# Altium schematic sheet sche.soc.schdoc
size 594 x 419 mm; Symbol: Sheet-Symbol_A4; Border: 1; Title Block Position: 3; Width: 2338; Height: 1652; Region Start: 1; X Region Count: 6; Y Region Count: 4; Blade Width: 10; Title Block: 1; @Board Name: NandFlash; @Create Time: 14:00:03; @Update Time: 18:33:35; Company: 嘉立创EDA; Version: V1.0; Page Size: A4; @Project Name: 木马派(Mumap) Linux卡片电脑-RV1106G; @Page Count: 10; @Update Date: 2025-03-03; @Create Date: 2024-10-19; @Schematic Name: Schematic1; @Page No: 1; @Page Name: RV1106G; Device: Sheet-Symbol_A4
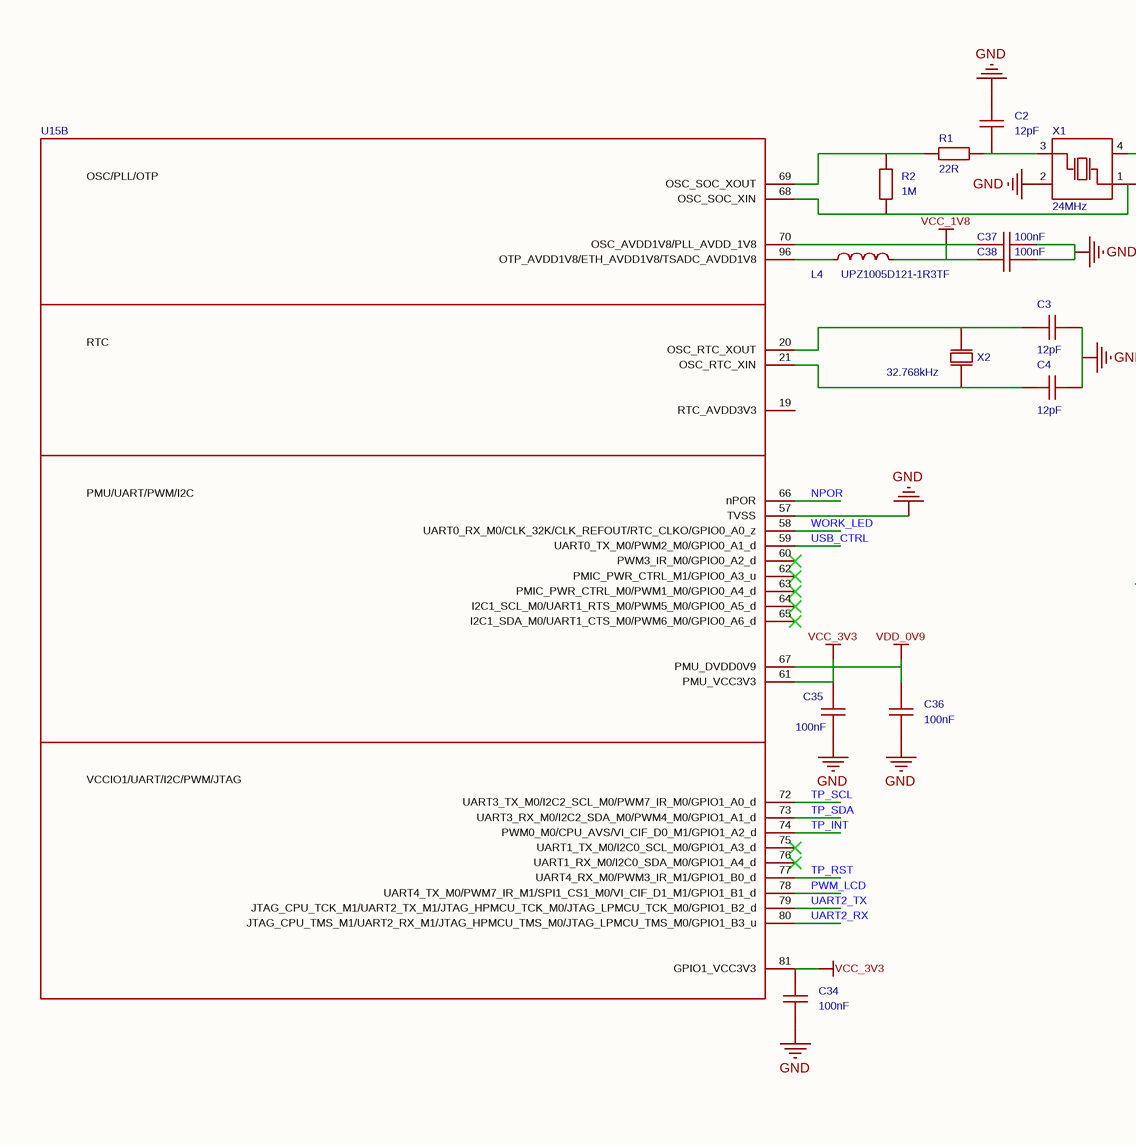
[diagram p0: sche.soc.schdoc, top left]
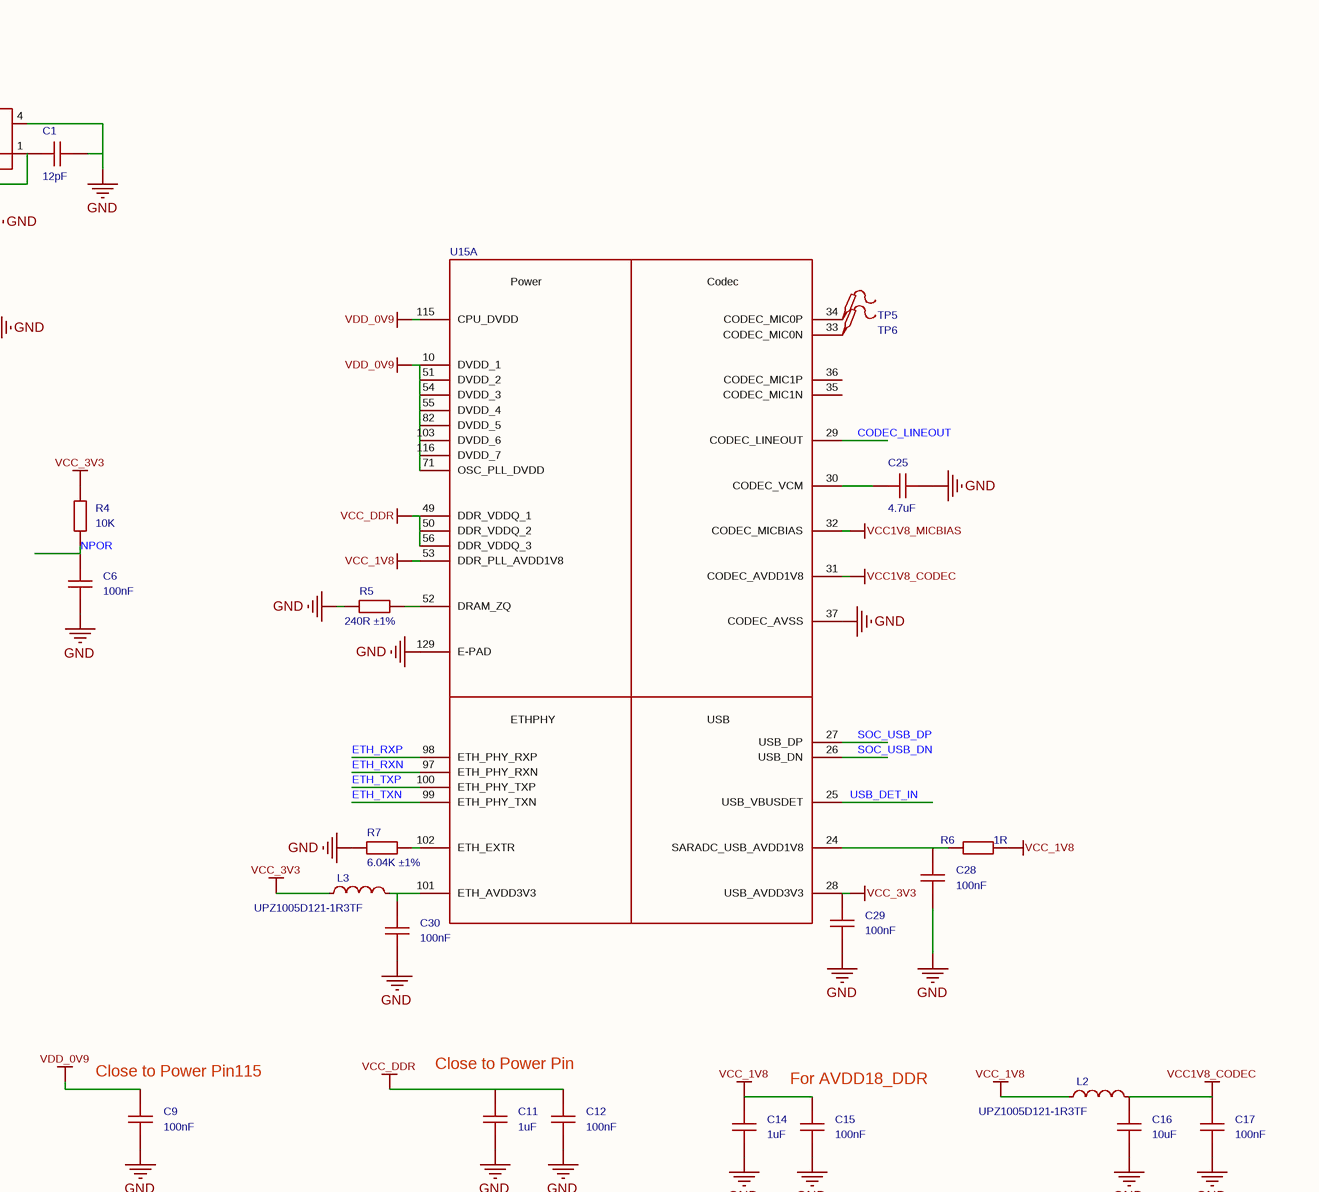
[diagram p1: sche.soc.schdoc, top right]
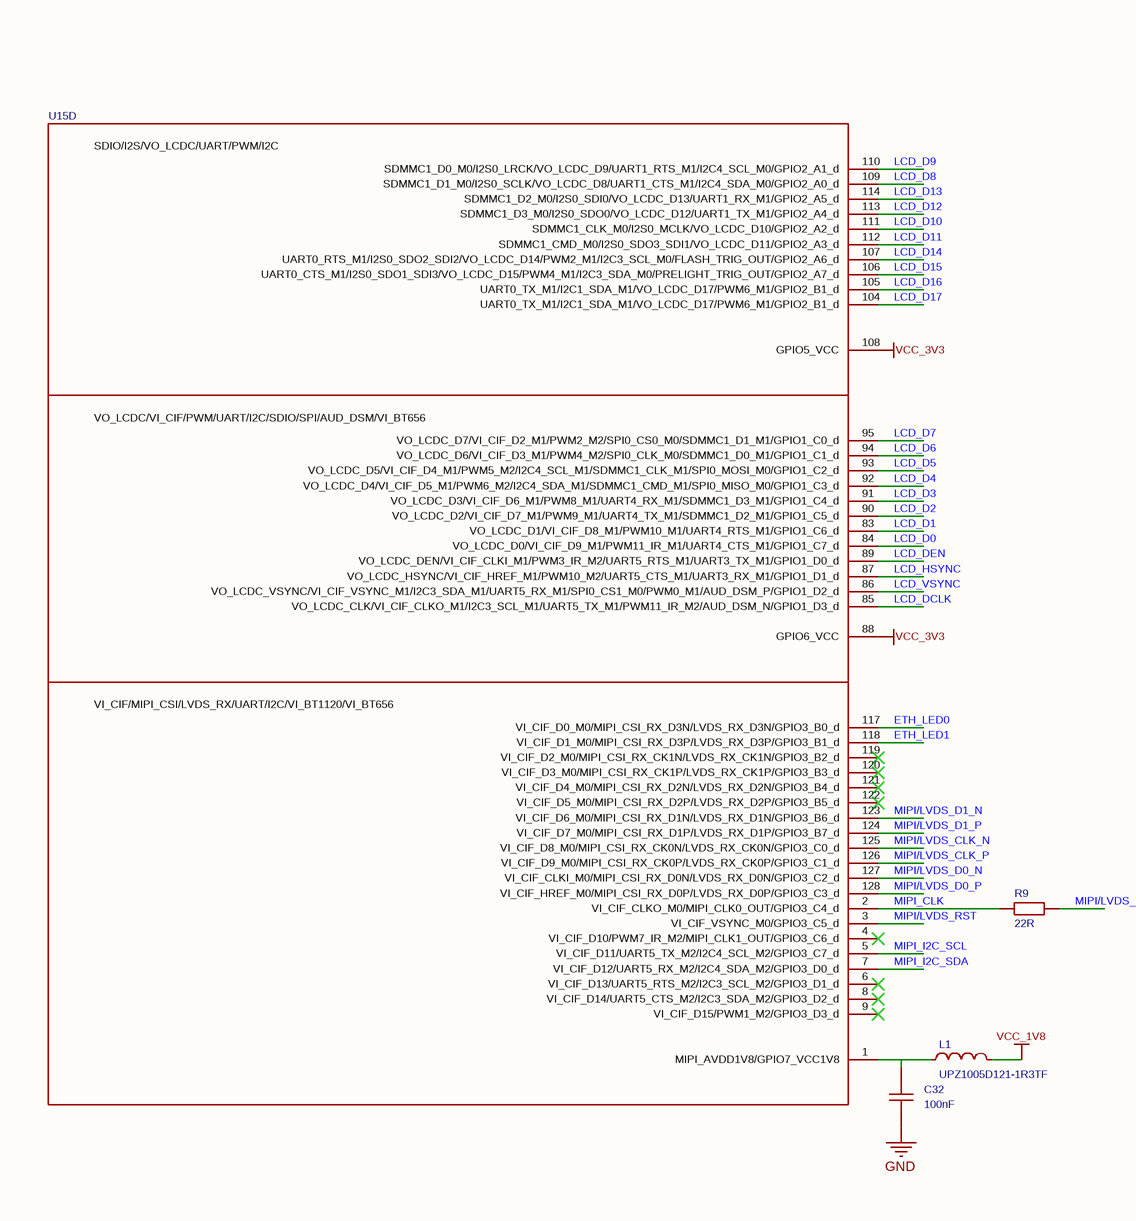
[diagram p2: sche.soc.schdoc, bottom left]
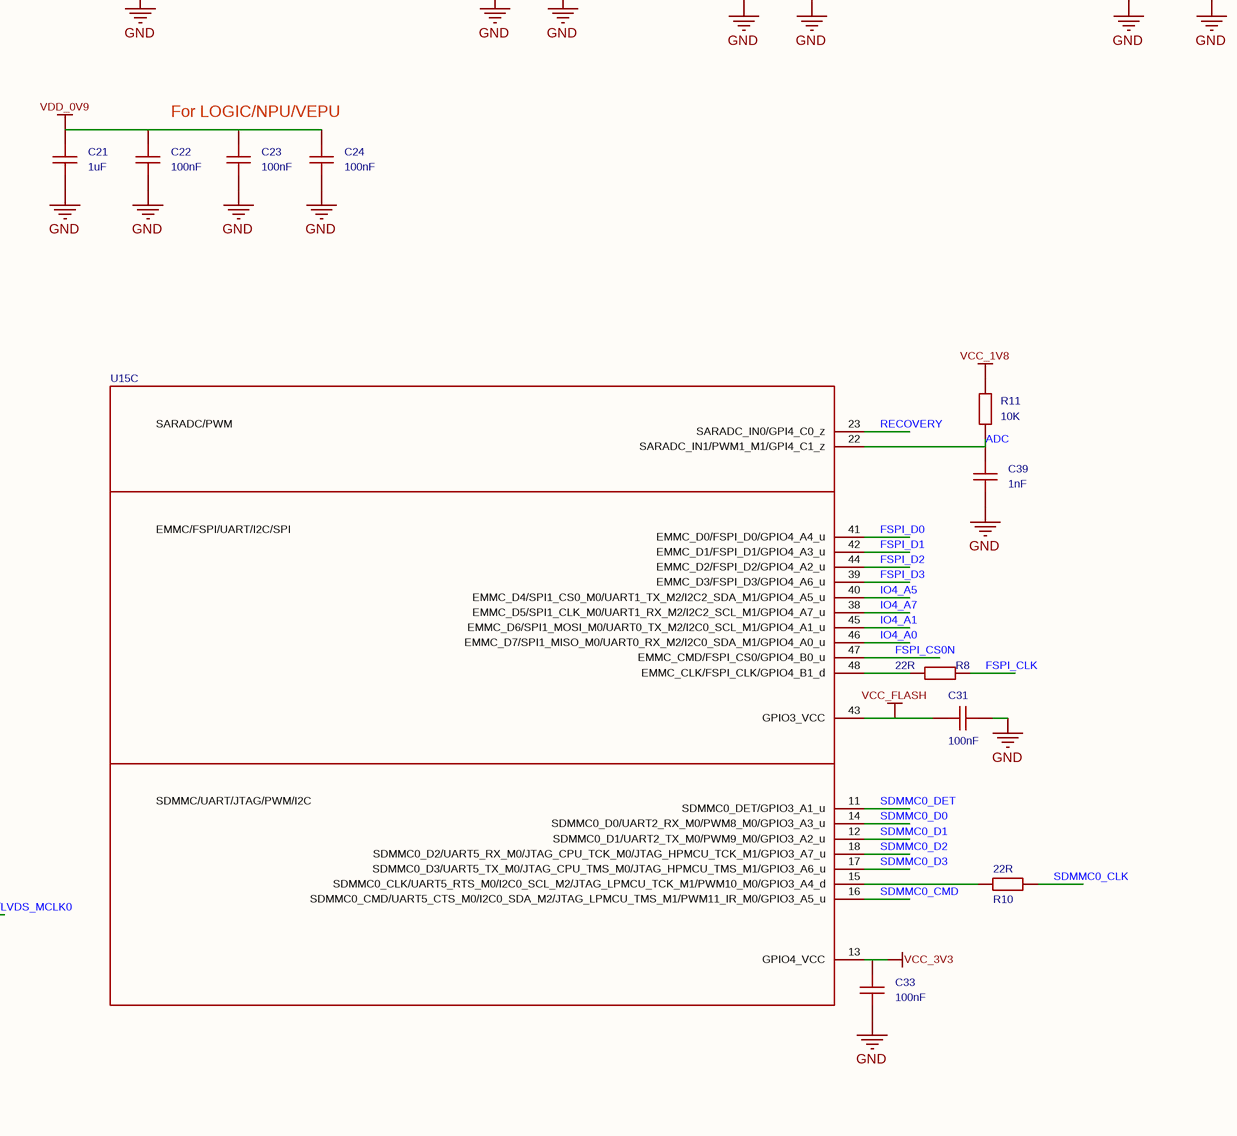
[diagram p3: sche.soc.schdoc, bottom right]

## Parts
C1  12pF  [C0402]
C2  12pF  [C0402]
C3  12pF  [C0402]
C4  12pF  [C0402]
C6  100nF  [C0402]
C9  100nF  [C0402]
C11  1uF  [C0402]
C12  100nF  [C0402]
C14  1uF  [C0402]
C15  100nF  [C0402]
C16  10uF  [C0603]
C17  100nF  [C0402]
C21  1uF  [C0402]
C22  100nF  [C0402]
C23  100nF  [C0402]
C24  100nF  [C0402]
C25  4.7uF  [C0603]
C28  100nF  [C0402]
C29  100nF  [C0402]
C30  100nF  [C0402]
C31  100nF  [C0402]
C32  100nF  [C0402]
C33  100nF  [C0402]
C34  100nF  [C0402]
C35  100nF  [C0402]
C36  100nF  [C0402]
C37  100nF  [C0402]
C38  100nF  [C0402]
C39  1nF  [C0402]
L1  UPZ1005D121-1R3TF  [L0402]
L2  UPZ1005D121-1R3TF  [L0402]
L3  UPZ1005D121-1R3TF  [L0402]
L4  UPZ1005D121-1R3TF  [L0402]
R1  22R  [R0402]
R2  1M  [R0402]
R4  10K  [R0402]
R5  240R ±1%  [R0402]
R6  1R  [R0402]
R7  6.04K ±1%  [R0402]
R8  22R  [R0402]
R9  22R  [R0402]
R10  22R  [R0402]
R11  10K  [R0402]
TP5  (no value)  [Test-Point-0.5mm]
TP6  (no value)  [Test-Point-0.5mm]
U15  (no value)  [QFN-128_L12.3-W12.3-P0.35-TL-EP7.0-1]  (parts A,B,C,D of 4)
X1  24MHz  [CRYSTAL-SMD_4P-L2.0-W1.6-BL-A]
X2  32.768kHz  [CRYSTAL-SMD_2P-L2.0-W1.2]

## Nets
GND: C1.1 C2.2 C3.1 C4.1 C6.1 C9.1 C11.1 C12.1 C14.1 C15.1 C16.1 C17.1 C21.1 C22.1 C23.1 C24.1 C25.2 C28.1 C29.1 C30.1 C31.1 C32.1 C33.1 C34.1 C35.1 C36.1 C37.2 C38.2 C39.1 R5.1 R7.1 U15.37(CODEC_AVSS) U15.57(TVSS) U15.129(E-PAD) X1.2(GND) X1.4(GND)
VCC1V8_CODEC: C16.2 C17.2 L2.2 U15.31(CODEC_AVDD1V8)
VCC1V8_MICBIAS: U15.32(CODEC_MICBIAS)
VCC_1V8: C14.2 C15.2 C37.1 C38.1 L1.2 L2.1 L4.2 R6.2 R11.2 U15.53(DDR_PLL_AVDD1V8) U15.70(OSC_AVDD1V8/PLL_AVDD_1V8)
VCC_3V3: C29.2 C33.2 C34.2 C35.2 L3.1 R4.2 U15.13(GPIO4_VCC) U15.28(USB_AVDD3V3) U15.61(PMU_VCC3V3) U15.81(GPIO1_VCC3V3) U15.88(GPIO6_VCC) U15.108(GPIO5_VCC)
VCC_DDR: C11.2 C12.2 U15.49(DDR_VDDQ_1) U15.50(DDR_VDDQ_2) U15.56(DDR_VDDQ_3)
VCC_FLASH: C31.2 U15.43(GPIO3_VCC)
VDD_0V9: C9.2 C21.2 C22.2 C23.2 C24.2 C36.2 U15.10(DVDD_1) U15.51(DVDD_2) U15.54(DVDD_3) U15.55(DVDD_4) U15.67(PMU_DVDD0V9) U15.71(OSC_PLL_DVDD) U15.82(DVDD_5) U15.103(DVDD_6) U15.115(CPU_DVDD) U15.116(DVDD_7)
ADC: C39.2 R11.1 U15.22(SARADC_IN1/PWM1_M1/GPI4_C1_z)
CODEC_LINEOUT: U15.29(CODEC_LINEOUT)
ETH_LED0: U15.117(VI_CIF_D0_M0/MIPI_CSI_RX_D3N/LVDS_RX_D3N/GPIO3_B0_d)
ETH_LED1: U15.118(VI_CIF_D1_M0/MIPI_CSI_RX_D3P/LVDS_RX_D3P/GPIO3_B1_d)
ETH_RXN: U15.97(ETH_PHY_RXN)
ETH_RXP: U15.98(ETH_PHY_RXP)
ETH_TXN: U15.99(ETH_PHY_TXN)
ETH_TXP: U15.100(ETH_PHY_TXP)
FSPI_CLK: R8.2
FSPI_CS0N: U15.47(EMMC_CMD/FSPI_CS0/GPIO4_B0_u)
FSPI_D0: U15.41(EMMC_D0/FSPI_D0/GPIO4_A4_u)
FSPI_D1: U15.42(EMMC_D1/FSPI_D1/GPIO4_A3_u)
FSPI_D2: U15.44(EMMC_D2/FSPI_D2/GPIO4_A2_u)
FSPI_D3: U15.39(EMMC_D3/FSPI_D3/GPIO4_A6_u)
IO4_A0: U15.46(EMMC_D7/SPI1_MISO_M0/UART0_RX_M2/I2C0_SDA_M1/GPIO4_A0_u)
IO4_A1: U15.45(EMMC_D6/SPI1_MOSI_M0/UART0_TX_M2/I2C0_SCL_M1/GPIO4_A1_u)
IO4_A5: U15.40(EMMC_D4/SPI1_CS0_M0/UART1_TX_M2/I2C2_SDA_M1/GPIO4_A5_u)
IO4_A7: U15.38(EMMC_D5/SPI1_CLK_M0/UART1_RX_M2/I2C2_SCL_M1/GPIO4_A7_u)
LCD_D0: U15.84(VO_LCDC_D0/VI_CIF_D9_M1/PWM11_IR_M1/UART4_CTS_M1/GPIO1_C7_d)
LCD_D1: U15.83(VO_LCDC_D1/VI_CIF_D8_M1/PWM10_M1/UART4_RTS_M1/GPIO1_C6_d)
LCD_D2: U15.90(VO_LCDC_D2/VI_CIF_D7_M1/PWM9_M1/UART4_TX_M1/SDMMC1_D2_M1/GPIO1_C5_d)
LCD_D3: U15.91(VO_LCDC_D3/VI_CIF_D6_M1/PWM8_M1/UART4_RX_M1/SDMMC1_D3_M1/GPIO1_C4_d)
LCD_D4: U15.92(VO_LCDC_D4/VI_CIF_D5_M1/PWM6_M2/I2C4_SDA_M1/SDMMC1_CMD_M1/SPI0_MISO_M0/GPIO1_C3_d)
LCD_D5: U15.93(VO_LCDC_D5/VI_CIF_D4_M1/PWM5_M2/I2C4_SCL_M1/SDMMC1_CLK_M1/SPI0_MOSI_M0/GPIO1_C2_d)
LCD_D6: U15.94(VO_LCDC_D6/VI_CIF_D3_M1/PWM4_M2/SPI0_CLK_M0/SDMMC1_D0_M1/GPIO1_C1_d)
LCD_D7: U15.95(VO_LCDC_D7/VI_CIF_D2_M1/PWM2_M2/SPI0_CS0_M0/SDMMC1_D1_M1/GPIO1_C0_d)
LCD_D8: U15.109(SDMMC1_D1_M0/I2S0_SCLK/VO_LCDC_D8/UART1_CTS_M1/I2C4_SDA_M0/GPIO2_A0_d)
LCD_D9: U15.110(SDMMC1_D0_M0/I2S0_LRCK/VO_LCDC_D9/UART1_RTS_M1/I2C4_SCL_M0/GPIO2_A1_d)
LCD_D10: U15.111(SDMMC1_CLK_M0/I2S0_MCLK/VO_LCDC_D10/GPIO2_A2_d)
LCD_D11: U15.112(SDMMC1_CMD_M0/I2S0_SDO3_SDI1/VO_LCDC_D11/GPIO2_A3_d)
LCD_D12: U15.113(SDMMC1_D3_M0/I2S0_SDO0/VO_LCDC_D12/UART1_TX_M1/GPIO2_A4_d)
LCD_D13: U15.114(SDMMC1_D2_M0/I2S0_SDI0/VO_LCDC_D13/UART1_RX_M1/GPIO2_A5_d)
LCD_D14: U15.107(UART0_RTS_M1/I2S0_SDO2_SDI2/VO_LCDC_D14/PWM2_M1/I2C3_SCL_M0/FLASH_TRIG_OUT/GPIO2_A6_d)
LCD_D15: U15.106(UART0_CTS_M1/I2S0_SDO1_SDI3/VO_LCDC_D15/PWM4_M1/I2C3_SDA_M0/PRELIGHT_TRIG_OUT/GPIO2_A7_d)
LCD_D16: U15.105(UART0_TX_M1/I2C1_SDA_M1/VO_LCDC_D17/PWM6_M1/GPIO2_B1_d)
LCD_D17: U15.104(UART0_TX_M1/I2C1_SDA_M1/VO_LCDC_D17/PWM6_M1/GPIO2_B1_d)
LCD_DCLK: U15.85(VO_LCDC_CLK/VI_CIF_CLKO_M1/I2C3_SCL_M1/UART5_TX_M1/PWM11_IR_M2/AUD_DSM_N/GPIO1_D3_d)
LCD_DEN: U15.89(VO_LCDC_DEN/VI_CIF_CLKI_M1/PWM3_IR_M2/UART5_RTS_M1/UART3_TX_M1/GPIO1_D0_d)
LCD_HSYNC: U15.87(VO_LCDC_HSYNC/VI_CIF_HREF_M1/PWM10_M2/UART5_CTS_M1/UART3_RX_M1/GPIO1_D1_d)
LCD_VSYNC: U15.86(VO_LCDC_VSYNC/VI_CIF_VSYNC_M1/I2C3_SDA_M1/UART5_RX_M1/SPI0_CS1_M0/PWM0_M1/AUD_DSM_P/GPIO1_D2_d)
MIPI/LVDS_CLK_N: U15.125(VI_CIF_D8_M0/MIPI_CSI_RX_CK0N/LVDS_RX_CK0N/GPIO3_C0_d)
MIPI/LVDS_CLK_P: U15.126(VI_CIF_D9_M0/MIPI_CSI_RX_CK0P/LVDS_RX_CK0P/GPIO3_C1_d)
MIPI/LVDS_D0_N: U15.127(VI_CIF_CLKI_M0/MIPI_CSI_RX_D0N/LVDS_RX_D0N/GPIO3_C2_d)
MIPI/LVDS_D0_P: U15.128(VI_CIF_HREF_M0/MIPI_CSI_RX_D0P/LVDS_RX_D0P/GPIO3_C3_d)
MIPI/LVDS_D1_N: U15.123(VI_CIF_D6_M0/MIPI_CSI_RX_D1N/LVDS_RX_D1N/GPIO3_B6_d)
MIPI/LVDS_D1_P: U15.124(VI_CIF_D7_M0/MIPI_CSI_RX_D1P/LVDS_RX_D1P/GPIO3_B7_d)
MIPI/LVDS_MCLK0: R9.2
MIPI/LVDS_RST: U15.3(VI_CIF_VSYNC_M0/GPIO3_C5_d)
MIPI_CLK: R9.1 U15.2(VI_CIF_CLKO_M0/MIPI_CLK0_OUT/GPIO3_C4_d)
MIPI_I2C_SCL: U15.5(VI_CIF_D11/UART5_TX_M2/I2C4_SCL_M2/GPIO3_C7_d)
MIPI_I2C_SDA: U15.7(VI_CIF_D12/UART5_RX_M2/I2C4_SDA_M2/GPIO3_D0_d)
NPOR: C6.2 R4.1 U15.66(nPOR)
PWM_LCD: U15.78(UART4_TX_M0/PWM7_IR_M1/SPI1_CS1_M0/VI_CIF_D1_M1/GPIO1_B1_d)
RECOVERY: U15.23(SARADC_IN0/GPI4_C0_z)
SDMMC0_CLK: R10.2
SDMMC0_CMD: U15.16(SDMMC0_CMD/UART5_CTS_M0/I2C0_SDA_M2/JTAG_LPMCU_TMS_M1/PWM11_IR_M0/GPIO3_A5_u)
SDMMC0_D0: U15.14(SDMMC0_D0/UART2_RX_M0/PWM8_M0/GPIO3_A3_u)
SDMMC0_D1: U15.12(SDMMC0_D1/UART2_TX_M0/PWM9_M0/GPIO3_A2_u)
SDMMC0_D2: U15.18(SDMMC0_D2/UART5_RX_M0/JTAG_CPU_TCK_M0/JTAG_HPMCU_TCK_M1/GPIO3_A7_u)
SDMMC0_D3: U15.17(SDMMC0_D3/UART5_TX_M0/JTAG_CPU_TMS_M0/JTAG_HPMCU_TMS_M1/GPIO3_A6_u)
SDMMC0_DET: U15.11(SDMMC0_DET/GPIO3_A1_u)
SOC_USB_DN: U15.26(USB_DN)
SOC_USB_DP: U15.27(USB_DP)
TP_INT: U15.74(PWM0_M0/CPU_AVS/VI_CIF_D0_M1/GPIO1_A2_d)
TP_RST: U15.77(UART4_RX_M0/PWM3_IR_M1/GPIO1_B0_d)
TP_SCL: U15.72(UART3_TX_M0/I2C2_SCL_M0/PWM7_IR_M0/GPIO1_A0_d)
TP_SDA: U15.73(UART3_RX_M0/I2C2_SDA_M0/PWM4_M0/GPIO1_A1_d)
UART2_RX: U15.80(JTAG_CPU_TMS_M1/UART2_RX_M1/JTAG_HPMCU_TMS_M0/JTAG_LPMCU_TMS_M0/GPIO1_B3_u)
UART2_TX: U15.79(JTAG_CPU_TCK_M1/UART2_TX_M1/JTAG_HPMCU_TCK_M0/JTAG_LPMCU_TCK_M0/GPIO1_B2_d)
USB_CTRL: U15.59(UART0_TX_M0/PWM2_M0/GPIO0_A1_d)
USB_DET_IN: U15.25(USB_VBUSDET)
WORK_LED: U15.58(UART0_RX_M0/CLK_32K/CLK_REFOUT/RTC_CLKO/GPIO0_A0_z)
NetC1_2: C1.2 R2.1 U15.68(OSC_SOC_XIN) X1.1(OSC1)
NetC2_1: C2.1 R1.2 X1.3(OSC2)
NetC3_2: C3.2 U15.20(OSC_RTC_XOUT) X2.2(OSC2)
NetC4_2: C4.2 U15.21(OSC_RTC_XIN) X2.1(OSC1)
NetC25_1: C25.1 U15.30(CODEC_VCM)
NetC28_2: C28.2 R6.1 U15.24(SARADC_USB_AVDD1V8)
NetC30_2: C30.2 L3.2 U15.101(ETH_AVDD3V3)
NetC32_2: C32.2 L1.1 U15.1(MIPI_AVDD1V8/GPIO7_VCC1V8)
NetL4_1: L4.1 U15.96(OTP_AVDD1V8/ETH_AVDD1V8/TSADC_AVDD1V8)
NetR1_1: R1.1 R2.2 U15.69(OSC_SOC_XOUT)
NetR5_2: R5.2 U15.52(DRAM_ZQ)
NetR7_2: R7.2 U15.102(ETH_EXTR)
NetR8_1: R8.1 U15.48(EMMC_CLK/FSPI_CLK/GPIO4_B1_d)
NetR10_1: R10.1 U15.15(SDMMC0_CLK/UART5_RTS_M0/I2C0_SCL_M2/JTAG_LPMCU_TCK_M1/PWM10_M0/GPIO3_A4_d)
NetTP5_1: TP5.1 U15.34(CODEC_MIC0P)
NetTP6_1: TP6.1 U15.33(CODEC_MIC0N)

Not connected (* = marked no-connect by the designer): U15 4(VI_CIF_D10/PWM7_IR_M2/MIPI_CLK1_OUT/GPIO3_C6_d)* 6(VI_CIF_D13/UART5_RTS_M2/I2C3_SCL_M2/GPIO3_D1_d)* 8(VI_CIF_D14/UART5_CTS_M2/I2C3_SDA_M2/GPIO3_D2_d)* 9(VI_CIF_D15/PWM1_M2/GPIO3_D3_d)* 19(RTC_AVDD3V3) 35(CODEC_MIC1N) 36(CODEC_MIC1P) 60(PWM3_IR_M0/GPIO0_A2_d)* 62(PMIC_PWR_CTRL_M1/GPIO0_A3_u)* 63(PMIC_PWR_CTRL_M0/PWM1_M0/GPIO0_A4_d)* 64(I2C1_SCL_M0/UART1_RTS_M0/PWM5_M0/GPIO0_A5_d)* 65(I2C1_SDA_M0/UART1_CTS_M0/PWM6_M0/GPIO0_A6_d)* 75(UART1_TX_M0/I2C0_SCL_M0/GPIO1_A3_d)* 76(UART1_RX_M0/I2C0_SDA_M0/GPIO1_A4_d)* 119(VI_CIF_D2_M0/MIPI_CSI_RX_CK1N/LVDS_RX_CK1N/GPIO3_B2_d)* 120(VI_CIF_D3_M0/MIPI_CSI_RX_CK1P/LVDS_RX_CK1P/GPIO3_B3_d)* 121(VI_CIF_D4_M0/MIPI_CSI_RX_D2N/LVDS_RX_D2N/GPIO3_B4_d)* 122(VI_CIF_D5_M0/MIPI_CSI_RX_D2P/LVDS_RX_D2P/GPIO3_B5_d)*

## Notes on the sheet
- (near C9) Close to Power Pin115
- Close to Power Pin
- (near C15) For AVDD18_DDR
- For LOGIC/NPU/VEPU

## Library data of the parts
C1-C4 C6 C32 C34-C38 = CAP_0402: ConvertToPcb: yes; SymbolName: CapAcitance; ModelId: 36a51122f27c49738f86b3bfa98863e0; ModelName: C0402_L1.0-W0.5-H0.5; ModelTransform: 39.37,19.685,0,0,0,0,0,0,0
C9 C11 C12 C14 C15 C17 C21-C24 C28-C31 C33 C39 = CAP_0402: Symbol: CapAcitance; ConvertToPcb: yes; ModelId: 36a51122f27c49738f86b3bfa98863e0; ModelName: C0402_L1.0-W0.5-H0.5; ModelTransform: 39.37,19.685,0,0,0,0,0,0,0
C16 C25 = CAP_0603: Symbol: CapAcitance; ConvertToPcb: yes; ModelId: ac125912035d415993ca9572d50418b1; ModelName: C0603_L1.6-W0.8-H0.8; ModelTransform: 62.992,31.496,0,0,0,0,0,0,0
L1-L4 = UPZ1005D121-1R3TF: 标称阻抗@测试频率:120Ω@100MHz;误差:±25%;直流电阻(RDC):90mΩ;; Manufacturer: Sunlord(顺络); AddInBom: yes; ModelId: d8d36575a3234d4790bfa765c88664a7; ModelName: L0402_L1.0-W0.5-H0.5_BEAD; ModelTransform: 39.37,19.685,0,0,0,0,0,0.0005,0; Tolerance: ±25%; DC Resistance: 90mΩ; Current Rating: 1.3A; Circuits: 1
R1 R2 R4-R11 = Res_0402: Symbol: 电阻; ConvertToPcb: yes; ModelId: 671aefced39d4c318694bba8bd8efd39; ModelName: R0402_L1.0-W0.5-H0.5; ModelTransform: 39.37,19.685,0,0,0,0,0,0.0005,0
TP5 TP6 = Test-Point: Test Point 测试点; AddInBom: yes
U15 = RV1106: Rockchip RV1106; Relevance: []; AddInBom: yes; ModelId: 9579931cf9fa4287a51ef595d9cfb3a3; ModelTransform: 485.04,485.04,28.740000000000002,0,0,0,0,0,0
X1 = TAXM24M4ZDBCCT2T: 晶振类型:贴片晶振;频率:24MHz;常温频差:±20ppm;外接负载电容:10pF;频率稳定度(全温):±15ppm;; Manufacturer: YJX(雅晶鑫); AddInBom: yes; ModelId: ff569852e08d42e6a0afc8f1b31cbda0; ModelTransform: 78.74,62.992,0,0,0,0,0,0,0; Crystal Type: 贴片晶振; Normal temperature Frequency Tolerance: ±20ppm; External load capacitor: 10pF; Frequency Stability(Full temperature range): ±15ppm; Equivalent Series Resistance (ESR): 80Ω
X2 = XKHEL89CGI-112YLC-32.768K: 晶振类型:贴片晶振;频率:32.768kHz;常温频差:±20ppm;外接负载电容:12.5pF;频率稳定度(全温):-;; Manufacturer: YXC(扬兴晶振); AddInBom: yes; ModelId: 0ef12d2de4aa45edaecb2da3a0d0b794; ModelTransform: 78.74,47.244,0,0,0,0,0,0,0; Crystal Type: 贴片晶振; Normal temperature Frequency Tolerance: ±20ppm; External load capacitor: 12.5pF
